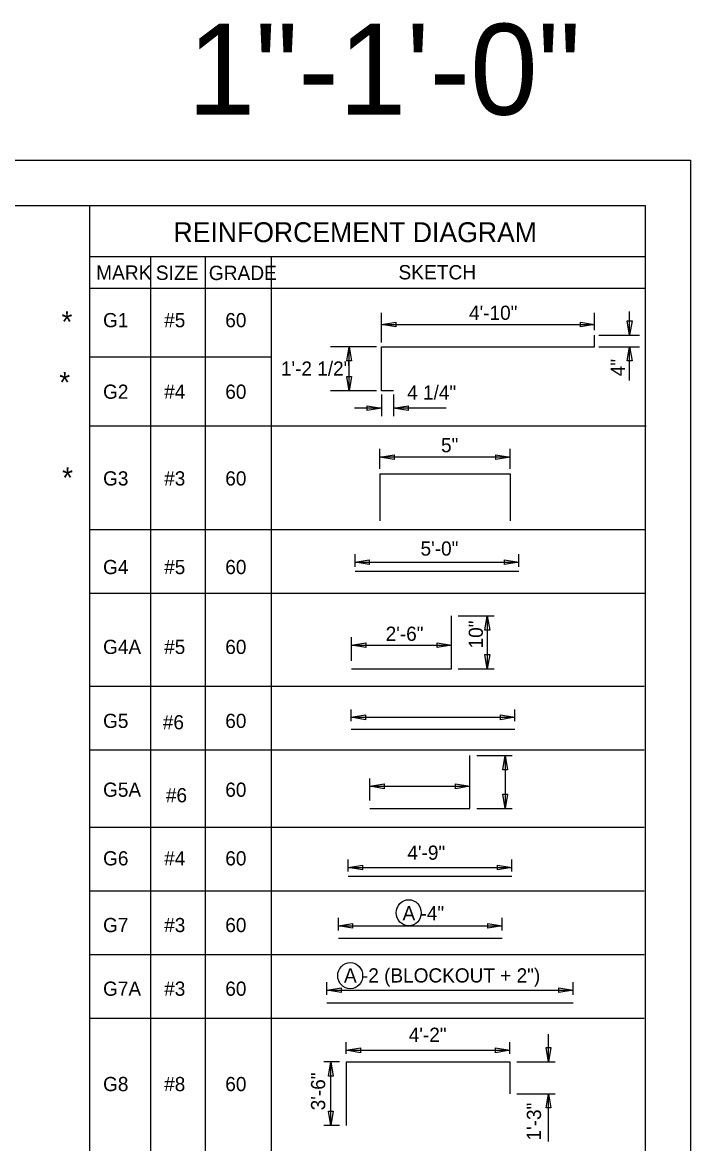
# Model space of a CAD drawing. Extents: x 0 to 34, y 0 to 23.5.
# Drawn here: x 26.65 to 34, y 11.18 to 23.51 of the extents above; entities that cross this region are included whole.
import ezdxf

# ---------------------------------------------------------------- set-up
doc = ezdxf.new("R2010")
doc.units = 0
for name, color, linetype in [('BORDER_ANNO_Cutsheet', 7, 'Continuous'), ('BRDG_ANNO_Anno-Sheet', 7, 'Continuous'), ('BRDG_ANNO_General-Notes', 7, 'Continuous'), ('BRDG_BASE_Obj-Line', 7, 'Continuous'), ('BRDG_BASE_Rebar', 7, 'Continuous'), ('Default', 7, 'Continuous')]:
    doc.layers.add(name, color=color, linetype=linetype)

# ---------------------------------------------------------------- blocks, each defined once
blk = doc.blocks.new('TERM')
at = {"layer": 'Default'}
for p, q in [((-1.6, -0.27), (-1.6, 0.27)), ((-1.6, 0.27), (0, 0)), ((0, 0), (-1.6, -0.27))]:
    blk.add_line(p, q, dxfattribs=at)

msp = doc.modelspace()

# ---------------------------------------------------------------- linework, layer by layer
at = {"layer": 'BORDER_ANNO_Cutsheet'}
msp.add_lwpolyline([(0, 22), (34, 22), (34, 0), (0, 0)], close=True, dxfattribs=at)
at = {"layer": 'BRDG_ANNO_Anno-Sheet'}
msp.add_lwpolyline([(1.5, 21.5), (33.5, 21.5), (33.5, 0.5), (1.5, 0.5)], close=True, dxfattribs=at)
at = {"layer": 'BRDG_ANNO_General-Notes'}
for p, q in [((30.601, 19.995), (30.601, 20.32)), ((32.945, 20.129), (32.945, 20.32)), ((33.303, 20.231), (33.356, 20.231)), ((33.329, 20.073), (33.303, 20.231)), ((33.329, 20.073), (33.329, 20.336)), ((33.356, 20.231), (33.329, 20.073)), ((30.601, 20.191), (30.759, 20.217)), ((30.601, 20.191), (32.945, 20.191)), ((30.759, 20.165), (30.601, 20.191)), ((30.759, 20.217), (30.759, 20.165)), ((32.788, 20.165), (32.788, 20.217)), ((32.788, 20.217), (32.945, 20.191)), ((32.945, 20.191), (32.788, 20.165)), ((32.992, 20.073), (33.439, 20.073)), ((30.547, 19.948), (30.04, 19.948)), ((30.218, 19.791), (30.244, 19.948)), ((30.244, 19.464), (30.244, 19.948)), ((30.244, 19.948), (30.271, 19.791)), ((32.992, 19.948), (33.439, 19.948)), ((33.303, 19.791), (33.329, 19.948)), ((33.329, 19.577), (33.329, 19.948)), ((33.329, 19.948), (33.356, 19.791)), ((30.271, 19.791), (30.218, 19.791)), ((33.356, 19.791), (33.303, 19.791)), ((30.218, 19.621), (30.271, 19.621)), ((30.244, 19.464), (30.218, 19.621)), ((30.271, 19.621), (30.244, 19.464)), ((30.547, 19.464), (30.04, 19.464)), ((30.601, 19.422), (30.601, 19.184)), ((30.734, 19.422), (30.734, 19.184)), ((30.601, 19.273), (30.302, 19.273)), ((30.444, 19.246), (30.444, 19.299)), ((30.444, 19.299), (30.601, 19.273)), ((30.601, 19.273), (30.444, 19.246)), ((30.734, 19.273), (30.892, 19.299)), ((31.311, 19.273), (30.734, 19.273)), ((30.892, 19.246), (30.734, 19.273)), ((30.892, 19.299), (30.892, 19.246)), ((30.583, 18.603), (30.583, 18.826)), ((32.016, 18.603), (32.016, 18.826)), ((32.016, 18.733), (30.583, 18.733)), ((30.309, 17.528), (30.309, 17.666)), ((32.11, 17.528), (32.11, 17.666)), ((30.309, 17.578), (30.466, 17.605)), ((30.309, 17.578), (32.11, 17.578)), ((30.466, 17.552), (30.309, 17.578)), ((30.466, 17.605), (30.466, 17.552)), ((31.952, 17.552), (31.952, 17.605)), ((31.952, 17.605), (32.11, 17.578)), ((32.11, 17.578), (31.952, 17.552)), ((31.445, 16.987), (31.839, 16.987)), ((31.738, 16.83), (31.764, 16.987)), ((31.764, 16.987), (31.764, 16.403)), ((31.764, 16.987), (31.791, 16.83)), ((31.791, 16.83), (31.738, 16.83)), ((30.27, 16.491), (30.27, 16.754)), ((30.27, 16.666), (30.427, 16.692)), ((30.27, 16.666), (31.37, 16.666)), ((30.427, 16.64), (30.27, 16.666)), ((30.427, 16.692), (30.427, 16.64)), ((31.213, 16.64), (31.213, 16.692)), ((31.213, 16.692), (31.37, 16.666)), ((31.37, 16.666), (31.213, 16.64)), ((31.738, 16.561), (31.791, 16.561)), ((31.764, 16.403), (31.738, 16.561)), ((31.791, 16.561), (31.764, 16.403)), ((31.445, 16.403), (31.839, 16.403)), ((30.267, 15.827), (30.267, 15.958)), ((32.068, 15.827), (32.068, 15.958)), ((30.267, 15.871), (30.424, 15.897)), ((30.267, 15.871), (32.068, 15.871)), ((30.424, 15.844), (30.267, 15.871)), ((30.424, 15.897), (30.424, 15.844)), ((31.91, 15.844), (31.91, 15.897)), ((31.91, 15.897), (32.068, 15.871)), ((32.068, 15.871), (31.91, 15.844)), ((31.648, 15.452), (32.037, 15.452)), ((31.936, 15.294), (31.962, 15.452)), ((31.962, 15.452), (31.962, 14.868)), ((31.962, 15.452), (31.988, 15.294)), ((31.988, 15.294), (31.936, 15.294)), ((30.473, 14.956), (30.473, 15.199)), ((31.573, 14.956), (31.573, 15.199)), ((30.473, 15.112), (30.63, 15.138)), ((30.473, 15.112), (31.573, 15.112)), ((30.63, 15.085), (30.473, 15.112)), ((30.63, 15.138), (30.63, 15.085)), ((31.416, 15.085), (31.416, 15.138)), ((31.416, 15.138), (31.573, 15.112)), ((31.573, 15.112), (31.416, 15.085)), ((31.936, 15.026), (31.988, 15.026)), ((31.962, 14.868), (31.936, 15.026)), ((31.988, 15.026), (31.962, 14.868)), ((31.648, 14.868), (32.037, 14.868)), ((30.234, 14.174), (30.234, 14.307)), ((32.035, 14.174), (32.035, 14.307)), ((30.234, 14.22), (30.392, 14.246)), ((30.234, 14.22), (32.035, 14.22)), ((30.392, 14.194), (30.234, 14.22)), ((30.392, 14.246), (30.392, 14.194)), ((31.877, 14.194), (31.877, 14.246)), ((31.877, 14.246), (32.035, 14.22)), ((32.035, 14.22), (31.877, 14.194)), ((30.126, 13.527), (30.126, 13.666)), ((30.126, 13.578), (30.283, 13.604)), ((30.126, 13.578), (31.927, 13.578)), ((30.283, 13.552), (30.126, 13.578)), ((30.283, 13.604), (30.283, 13.552)), ((31.769, 13.552), (31.769, 13.604)), ((31.769, 13.604), (31.927, 13.578)), ((31.927, 13.578), (31.769, 13.552)), ((31.927, 13.527), (31.927, 13.666)), ((30, 12.819), (30, 12.957)), ((32.708, 12.819), (32.708, 12.957)), ((30, 12.869), (30.157, 12.896)), ((30, 12.869), (32.708, 12.869)), ((30.157, 12.843), (30, 12.869)), ((30.157, 12.896), (30.157, 12.843)), ((32.551, 12.843), (32.551, 12.896)), ((32.551, 12.896), (32.708, 12.869)), ((32.708, 12.869), (32.551, 12.843)), ((32.437, 12.082), (32.437, 12.387)), ((30.212, 12.169), (30.212, 12.296)), ((30.212, 12.208), (30.37, 12.234)), ((30.37, 12.234), (30.37, 12.182)), ((31.856, 12.182), (31.856, 12.234)), ((31.856, 12.234), (32.013, 12.208)), ((32.013, 12.169), (32.013, 12.296)), ((32.411, 12.239), (32.464, 12.239)), ((32.437, 12.082), (32.411, 12.239)), ((32.464, 12.239), (32.437, 12.082)), ((30.212, 12.208), (32.013, 12.208)), ((30.37, 12.182), (30.212, 12.208)), ((32.013, 12.208), (31.856, 12.182)), ((30.137, 12.082), (29.967, 12.082)), ((30.016, 11.924), (30.042, 12.082)), ((30.042, 11.381), (30.042, 12.082)), ((30.042, 12.082), (30.069, 11.924)), ((32.088, 12.082), (32.512, 12.082)), ((30.069, 11.924), (30.016, 11.924)), ((32.088, 11.731), (32.512, 11.731)), ((32.411, 11.574), (32.437, 11.731)), ((32.437, 11.206), (32.437, 11.731)), ((32.437, 11.731), (32.464, 11.574)), ((30.016, 11.539), (30.069, 11.539)), ((30.042, 11.381), (30.016, 11.539)), ((30.069, 11.539), (30.042, 11.381)), ((32.464, 11.574), (32.411, 11.574)), ((30.137, 11.381), (29.967, 11.381))]:
    msp.add_line(p, q, dxfattribs=at)
for centre in [(30.9, 13.721), (30.256, 13.029)]:
    msp.add_ellipse(centre, major_axis=(0, 0.144), ratio=0.952381, dxfattribs=at)
at = {"layer": 'BRDG_BASE_Obj-Line'}
for p, q in [((27.387, 21.499), (27.387, 7.095)), ((27.387, 20.941), (33.506, 20.941)), ((28.06, 20.941), (28.06, 7.095)), ((28.66, 20.941), (28.66, 7.095)), ((29.386, 20.941), (29.386, 7.095)), ((27.387, 20.591), (33.5, 20.591)), ((28.059, 20.308), (28.059, 10.039)), ((27.387, 19.835), (29.386, 19.835)), ((27.387, 19.076), (33.512, 19.076)), ((27.387, 17.938), (33.494, 17.938)), ((27.387, 17.237), (33.506, 17.237)), ((27.387, 16.214), (33.488, 16.214)), ((27.387, 15.513), (33.488, 15.513)), ((27.387, 14.663), (33.488, 14.663)), ((27.387, 13.963), (33.488, 13.963)), ((27.387, 13.262), (33.488, 13.262)), ((27.387, 12.562), (33.488, 12.562))]:
    msp.add_line(p, q, dxfattribs=at)
at = {"layer": 'BRDG_BASE_Rebar'}
for p, q in [((30.583, 18.548), (32.016, 18.548)), ((30.583, 18.548), (30.583, 18.033)), ((32.016, 18.548), (32.016, 18.033)), ((30.309, 17.48), (32.11, 17.48)), ((31.37, 16.403), (31.37, 16.987)), ((30.27, 16.403), (31.37, 16.403)), ((30.267, 15.74), (32.068, 15.74)), ((31.573, 14.868), (31.573, 15.452)), ((30.473, 14.868), (31.573, 14.868)), ((30.234, 14.123), (32.035, 14.123)), ((30.126, 13.44), (31.927, 13.44)), ((30, 12.731), (32.708, 12.731)), ((30.212, 12.082), (32.013, 12.082)), ((30.212, 12.082), (30.212, 11.381)), ((32.013, 12.082), (32.013, 11.731))]:
    msp.add_line(p, q, dxfattribs=at)
msp.add_lwpolyline([(30.734, 19.464), (30.601, 19.464), (30.601, 19.948), (32.945, 19.948), (32.945, 20.073)], dxfattribs=at)

# ---------------------------------------------------------------- block references
at = {"layer": 'BRDG_ANNO_General-Notes', "xscale": 0.09765625, "yscale": 0.0976318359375, "rotation": 180}
msp.add_blockref('TERM', (30.583, 18.733), dxfattribs=at)
at = {"layer": 'BRDG_ANNO_General-Notes', "xscale": 0.09765625, "yscale": 0.0976318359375}
msp.add_blockref('TERM', (32.016, 18.733), dxfattribs=at)

# ---------------------------------------------------------------- texts
at = {"layer": 'BRDG_ANNO_Anno-Sheet'}
msp.add_text('1"-1\'-0"', height=1, dxfattribs=at).set_placement((28.467, 22.5))
at = {"layer": 'BRDG_ANNO_General-Notes'}
for s, height, p in [('REINFORCEMENT DIAGRAM', 0.21875, (28.312, 21.098)), ('SIZE', 0.1576, (28.118, 20.682)), ('SKETCH', 0.1575, (30.787, 20.688)), ('MARK', 0.1576, (27.461, 20.684)), ('GRADE', 0.1575, (28.701, 20.681)), ('4\'-10"', 0.1562, (31.563, 20.243)), ('*', 0.229, (27.081, 20.108)), ('G1', 0.1562, (27.538, 20.162)), ('#5', 0.1562, (28.21, 20.162)), ('60', 0.1562, (28.882, 20.162)), ('1\'-2 1/2"', 0.1562, (29.494, 19.629)), ('*', 0.229, (27.056, 19.442)), ('G2', 0.1562, (27.538, 19.375)), ('#4', 0.1562, (28.21, 19.375)), ('60', 0.1562, (28.882, 19.375)), ('4 1/4"', 0.1562, (30.883, 19.366)), ('5"', 0.1562, (31.255, 18.787)), ('*', 0.229, (27.088, 18.392)), ('G3', 0.1562, (27.538, 18.421)), ('#3', 0.1562, (28.21, 18.421)), ('60', 0.1562, (28.882, 18.421)), ('5\'-0"', 0.1562, (31.03, 17.65)), ('G4', 0.1562, (27.538, 17.446)), ('#5', 0.1562, (28.21, 17.446)), ('60', 0.1562, (28.882, 17.446)), ('2\'-6"', 0.1562, (30.646, 16.712)), ('G4A', 0.1562, (27.538, 16.568)), ('#5', 0.1562, (28.21, 16.568)), ('60', 0.1562, (28.882, 16.568)), ('G5', 0.1562, (27.538, 15.754)), ('60', 0.1562, (28.882, 15.754)), ('#6', 0.1562, (28.195, 15.739)), ('G5A', 0.1562, (27.538, 14.997)), ('#6', 0.1562, (28.229, 14.936)), ('60', 0.1562, (28.882, 14.997)), ('4\'-9"', 0.1562, (30.885, 14.304)), ('G6', 0.1562, (27.538, 14.242)), ('#4', 0.1562, (28.21, 14.242)), ('60', 0.1562, (28.882, 14.242)), ('A -4"', 0.1562, (30.832, 13.638)), ('G7', 0.1562, (27.538, 13.508)), ('#3', 0.1562, (28.21, 13.508)), ('60', 0.1562, (28.882, 13.508)), ('A -2 (BLOCKOUT + 2")', 0.15625, (30.188, 12.954)), ('G7A', 0.1562, (27.538, 12.808)), ('#3', 0.1562, (28.21, 12.808)), ('60', 0.1562, (28.882, 12.808)), ('4\'-2"', 0.1562, (30.9, 12.301)), ('G8', 0.1562, (27.538, 11.759)), ('#8', 0.1562, (28.21, 11.759)), ('60', 0.1562, (28.882, 11.759))]:
    msp.add_text(s, height=height, dxfattribs=at).set_placement(p)
for s, p in [('4"', (33.278, 19.623)), ('10"', (31.716, 16.629)), ('3\'-6"', (29.981, 11.548)), ('1\'-3"', (32.355, 11.216))]:
    msp.add_text(s, height=0.1562, rotation=90, dxfattribs=at).set_placement(p)

doc.saveas('drawing.dxf')
